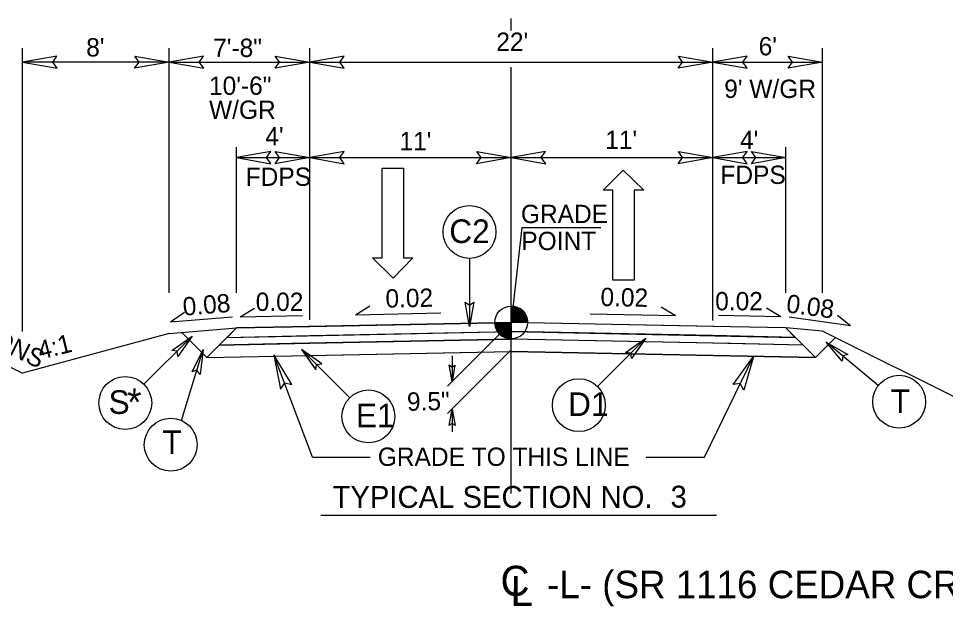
# Model space of a CAD drawing. Extents: x 573732 to 574187, y -53389 to -53257.
# Drawn here: x 573830.3 to 573880.9, y -53355.4 to -53323.3 of the extents above; entities that cross this region are included whole.
import ezdxf

# ---------------------------------------------------------------- set-up
doc = ezdxf.new("R2010")
doc.units = 0
for name, color, linetype in [('Old_Level_11', 7, 'Continuous'), ('Prop Dimension', 7, 'Continuous'), ('Prop Lane Arrow CELL', 7, 'Continuous'), ('Prop Shade Light', 7, 'Continuous'), ('Prop Shade Medium', 7, 'Continuous'), ('Typical Grade Point Symbol CELL', 7, 'Continuous'), ('Typical ID Circle CELL', 7, 'Continuous'), ('Typical Pavement Slope CELL', 7, 'Continuous'), ('Typical Pavement Slope Information CELL', 7, 'Continuous'), ('Typical Shoulder Slope CELL', 7, 'Continuous'), ('Typical Shoulder Slope Information CELL', 7, 'Continuous'), ('Typical Slope Point Local CELL', 7, 'Continuous'), ('Typical Terminator CELL', 7, 'Continuous'), ('Typical Text Centerline CELL', 7, 'Continuous'), ('Typical Text General CELL', 7, 'Continuous'), ('Typical Text Grade Point CELL', 7, 'Continuous'), ('Typical Text ID Circle CELL', 7, 'Continuous'), ('Typical Text Label CELL', 7, 'Continuous')]:
    doc.layers.add(name, color=color, linetype=linetype)

msp = doc.modelspace()

# ---------------------------------------------------------------- linework, layer by layer
at = {"layer": 'Old_Level_11'}
for points in [[(573854.103, -53342.22), (573853.948, -53343.12), (573853.788, -53342.215), (573853.948, -53342.33)], [(573853.793, -53345.52), (573853.948, -53344.62), (573854.108, -53345.525), (573853.948, -53345.41)]]:
    msp.add_lwpolyline(points, close=True, dxfattribs=at)
at = {"layer": 'Prop Dimension'}
for p, q in [((573830.501, -53340.385), (573830.501, -53324.924)), ((573838.501, -53338.27), (573838.501, -53324.924)), ((573846.171, -53339.759), (573846.171, -53324.924)), ((573868.171, -53339.784), (573868.171, -53324.924)), ((573874.171, -53338.27), (573874.171, -53324.924)), ((573838.501, -53325.68), (573830.501, -53325.68)), ((573838.501, -53325.68), (573846.171, -53325.68)), ((573846.171, -53325.68), (573868.171, -53325.68)), ((573868.171, -53325.68), (573874.171, -53325.68)), ((573842.171, -53338.27), (573842.171, -53330.32)), ((573872.171, -53338.27), (573872.171, -53330.32)), ((573842.171, -53330.896), (573846.171, -53330.896)), ((573846.171, -53330.896), (573857.171, -53330.896)), ((573857.171, -53330.896), (573868.171, -53330.896)), ((573868.171, -53330.896), (573872.171, -53330.896)), ((573857.747, -53334.719), (573857.171, -53339.896)), ((573857.747, -53334.719), (573862.067, -53334.719)), ((573857.172, -53339.897), (573853.701, -53343.367)), ((573857.172, -53341.397), (573853.701, -53344.868)), ((573846.331, -53347.251), (573844.209, -53341.657)), ((573853.948, -53341.723), (573853.948, -53343.12)), ((573867.717, -53347.251), (573870.391, -53341.745)), ((573853.948, -53344.62), (573853.948, -53345.874)), ((573846.331, -53347.251), (573849.471, -53347.251)), ((573864.533, -53347.251), (573867.717, -53347.251))]:
    msp.add_line(p, q, dxfattribs=at)
at = {"layer": 'Prop Lane Arrow CELL'}
for p, q in [((573850.13, -53336.375), (573850.13, -53331.475)), ((573850.13, -53331.475), (573851.285, -53331.475)), ((573851.285, -53331.475), (573851.285, -53336.375)), ((573862.201, -53332.683), (573863.286, -53331.581)), ((573863.286, -53331.581), (573864.406, -53332.683)), ((573862.726, -53332.683), (573862.201, -53332.683)), ((573862.726, -53337.583), (573862.726, -53332.683)), ((573864.406, -53332.683), (573863.881, -53332.683)), ((573863.881, -53332.683), (573863.881, -53337.583)), ((573850.725, -53337.477), (573849.605, -53336.375)), ((573849.605, -53336.375), (573850.13, -53336.375)), ((573851.81, -53336.375), (573850.725, -53337.477)), ((573851.285, -53336.375), (573851.81, -53336.375)), ((573863.881, -53337.583), (573862.726, -53337.583))]:
    msp.add_line(p, q, dxfattribs=at)
at = {"layer": 'Prop Shade Light'}
for p, q in [((573857.171, -53339.896), (573845.175, -53340.136)), ((573869.166, -53340.136), (573857.171, -53339.896)), ((573842.171, -53340.198), (573841.66, -53340.708)), ((573845.175, -53340.136), (573842.171, -53340.198)), ((573845.185, -53340.636), (573857.161, -53340.397)), ((573857.161, -53340.397), (573857.161, -53340.396)), ((573857.161, -53340.396), (573857.171, -53340.396)), ((573857.171, -53340.396), (573857.181, -53340.396)), ((573857.181, -53340.396), (573857.181, -53340.397)), ((573857.181, -53340.397), (573869.156, -53340.636)), ((573872.171, -53340.198), (573869.166, -53340.136)), ((573872.681, -53340.708), (573872.171, -53340.198)), ((573841.66, -53340.708), (573845.185, -53340.636)), ((573869.156, -53340.636), (573872.681, -53340.708))]:
    msp.add_line(p, q, dxfattribs=at)
at = {"layer": 'Prop Shade Medium'}
for p, q in [((573841.234, -53341.134), (573840.554, -53341.815)), ((573845.194, -53341.053), (573841.234, -53341.134)), ((573873.107, -53341.134), (573869.148, -53341.053)), ((573873.787, -53341.815), (573873.107, -53341.134)), ((573840.554, -53341.815), (573845.207, -53341.719)), ((573845.207, -53341.719), (573857.139, -53341.481)), ((573857.139, -53341.481), (573857.139, -53341.479)), ((573857.139, -53341.479), (573857.171, -53341.48)), ((573857.171, -53341.48), (573857.202, -53341.479)), ((573857.202, -53341.479), (573857.202, -53341.481)), ((573857.202, -53341.481), (573869.135, -53341.719)), ((573869.135, -53341.719), (573873.787, -53341.815))]:
    msp.add_line(p, q, dxfattribs=at)
for points in [[(573857.171, -53340.813), (573857.152, -53340.814), (573845.194, -53341.053)], [(573869.148, -53341.053), (573857.189, -53340.814), (573857.171, -53340.813)]]:
    msp.add_lwpolyline(points, dxfattribs=at)
at = {"layer": 'Typical Grade Point Symbol CELL'}
for p, q in [((573857.172, -53339.897), (573857.172, -53339.001)), ((573856.276, -53339.897), (573857.172, -53339.897)), ((573857.17, -53340.792), (573857.172, -53339.897)), ((573857.172, -53339.897), (573857.17, -53340.792)), ((573858.067, -53339.897), (573857.172, -53339.897))]:
    msp.add_line(p, q, dxfattribs=at)
for points in [[(573857.18, -53339.001), (573857.18, -53339.001), (573857.18, -53339.897)], [(573857.197, -53339.001), (573857.197, -53339.897)], [(573857.215, -53339.003), (573857.215, -53339.897)], [(573857.233, -53339.003), (573857.233, -53339.897)], [(573857.251, -53339.005), (573857.251, -53339.897)], [(573857.269, -53339.007), (573857.269, -53339.897)], [(573857.287, -53339.009), (573857.287, -53339.897)], [(573857.305, -53339.011), (573857.305, -53339.897)], [(573857.323, -53339.013), (573857.323, -53339.897)], [(573857.341, -53339.017), (573857.341, -53339.897)], [(573857.359, -53339.021), (573857.359, -53339.897)], [(573857.377, -53339.025), (573857.377, -53339.897)], [(573857.394, -53339.029), (573857.394, -53339.897)], [(573857.412, -53339.035), (573857.412, -53339.897)], [(573857.43, -53339.039), (573857.43, -53339.897)], [(573857.448, -53339.045), (573857.448, -53339.897)], [(573857.466, -53339.051), (573857.466, -53339.897)], [(573857.484, -53339.057), (573857.484, -53339.897)], [(573857.502, -53339.065), (573857.502, -53339.897)], [(573857.52, -53339.073), (573857.52, -53339.897)], [(573857.538, -53339.081), (573857.538, -53339.897)], [(573857.556, -53339.089), (573857.556, -53339.897)], [(573857.573, -53339.097), (573857.573, -53339.897)], [(573857.591, -53339.107), (573857.591, -53339.897)], [(573857.609, -53339.117), (573857.609, -53339.897)], [(573857.627, -53339.127), (573857.627, -53339.897)], [(573857.645, -53339.137), (573857.645, -53339.897)], [(573857.663, -53339.149), (573857.663, -53339.897)], [(573857.681, -53339.16), (573857.681, -53339.897)], [(573857.699, -53339.174), (573857.699, -53339.897)], [(573857.717, -53339.186), (573857.717, -53339.897)], [(573857.735, -53339.2), (573857.735, -53339.897)], [(573857.752, -53339.216), (573857.752, -53339.897)], [(573857.77, -53339.232), (573857.77, -53339.897)], [(573857.788, -53339.248), (573857.788, -53339.897)], [(573857.806, -53339.266), (573857.806, -53339.897)], [(573857.824, -53339.284), (573857.824, -53339.897)], [(573857.842, -53339.304), (573857.842, -53339.897)], [(573857.86, -53339.326), (573857.86, -53339.897)], [(573857.878, -53339.347), (573857.878, -53339.897)], [(573857.896, -53339.371), (573857.896, -53339.897)], [(573857.914, -53339.397), (573857.914, -53339.897)], [(573856.28, -53339.897), (573856.28, -53339.994)], [(573856.298, -53339.897), (573856.298, -53340.099)], [(573856.316, -53339.897), (573856.316, -53340.163)], [(573856.334, -53339.897), (573856.334, -53340.217)], [(573856.352, -53339.897), (573856.352, -53340.259)], [(573856.37, -53339.897), (573856.37, -53340.296)], [(573856.388, -53339.897), (573856.388, -53340.33)], [(573856.406, -53339.897), (573856.406, -53340.362)], [(573856.424, -53339.897), (573856.424, -53340.39)], [(573856.442, -53339.897), (573856.442, -53340.416)], [(573856.459, -53339.897), (573856.459, -53340.44)], [(573856.477, -53339.897), (573856.477, -53340.461)], [(573856.495, -53339.897), (573856.495, -53340.483)], [(573856.513, -53339.897), (573856.513, -53340.503)], [(573856.531, -53339.897), (573856.531, -53340.523)], [(573856.549, -53339.897), (573856.549, -53340.541)], [(573856.567, -53339.897), (573856.567, -53340.557)], [(573856.585, -53339.897), (573856.585, -53340.573)], [(573856.603, -53339.897), (573856.603, -53340.589)], [(573856.621, -53339.897), (573856.621, -53340.603)], [(573856.639, -53339.897), (573856.639, -53340.617)], [(573856.656, -53339.897), (573856.656, -53340.628)], [(573856.674, -53339.897), (573856.674, -53340.64)], [(573856.692, -53339.897), (573856.692, -53340.652)], [(573856.71, -53339.897), (573856.71, -53340.664)], [(573856.728, -53339.897), (573856.728, -53340.674)], [(573856.746, -53339.897), (573856.746, -53340.684)], [(573856.764, -53339.897), (573856.764, -53340.694)], [(573856.782, -53339.897), (573856.782, -53340.702)], [(573856.8, -53339.897), (573856.8, -53340.71)], [(573856.818, -53339.897), (573856.818, -53340.718)], [(573856.835, -53339.897), (573856.835, -53340.726)], [(573856.853, -53339.897), (573856.853, -53340.734)], [(573856.871, -53339.897), (573856.871, -53340.74)], [(573856.889, -53339.897), (573856.889, -53340.746)], [(573856.907, -53339.897), (573856.907, -53340.752)], [(573856.925, -53339.897), (573856.925, -53340.756)], [(573856.943, -53339.897), (573856.943, -53340.762)], [(573856.961, -53339.897), (573856.961, -53340.766)], [(573856.979, -53339.897), (573856.979, -53340.77)], [(573856.997, -53339.897), (573856.997, -53340.774)], [(573857.014, -53339.897), (573857.014, -53340.778)], [(573857.032, -53339.897), (573857.032, -53340.78)], [(573857.05, -53339.897), (573857.05, -53340.784)], [(573857.068, -53339.897), (573857.068, -53340.786)], [(573857.086, -53339.897), (573857.086, -53340.788)], [(573857.104, -53339.897), (573857.104, -53340.79)], [(573857.122, -53339.897), (573857.122, -53340.79)], [(573857.14, -53339.897), (573857.14, -53340.792)], [(573857.158, -53339.897), (573857.158, -53340.792), (573857.158, -53340.792)], [(573857.932, -53339.425), (573857.932, -53339.897)], [(573857.949, -53339.455), (573857.949, -53339.897)], [(573857.967, -53339.487), (573857.967, -53339.897)], [(573857.985, -53339.524), (573857.985, -53339.897)], [(573858.003, -53339.566), (573858.003, -53339.897)], [(573858.021, -53339.616), (573858.021, -53339.897)], [(573858.039, -53339.678), (573858.039, -53339.897)], [(573858.057, -53339.769), (573858.057, -53339.897)]]:
    msp.add_lwpolyline(points, dxfattribs=at)
msp.add_circle((573857.171, -53339.896), 0.895, dxfattribs=at)
for start, end in [(359.9905, 89.9905), (179.9905, 269.9905)]:
    msp.add_arc((573857.171, -53339.896), 0.895, start, end, dxfattribs=at)
at = {"layer": 'Typical ID Circle CELL'}
for p, q in [((573854.895, -53336.395), (573854.895, -53340.123)), ((573837.122, -53343.272), (573839.759, -53340.636)), ((573861.885, -53343.387), (573864.523, -53340.752)), ((573839.178, -53345.252), (573840.357, -53341.379)), ((573848.357, -53344.005), (573845.72, -53341.369)), ((573877.21, -53343.336), (573874.369, -53340.97))]:
    msp.add_line(p, q, dxfattribs=at)
for centre in [(573854.895, -53334.953), (573836.103, -53344.292), (573878.349, -53344.223), (573860.866, -53344.408), (573849.376, -53345.025), (573838.585, -53346.567)]:
    msp.add_circle(centre, 1.443, dxfattribs=at)
at = {"layer": 'Typical Pavement Slope CELL'}
for p, q in [((573846.171, -53340.116), (573857.171, -53339.896)), ((573868.171, -53340.116), (573857.171, -53339.896)), ((573846.171, -53340.616), (573857.181, -53340.396)), ((573868.171, -53340.616), (573857.161, -53340.396)), ((573846.171, -53341.033), (573857.171, -53340.813)), ((573868.171, -53341.033), (573857.171, -53340.813)), ((573846.171, -53341.7), (573857.171, -53341.48)), ((573868.171, -53341.7), (573857.171, -53341.48))]:
    msp.add_line(p, q, dxfattribs=at)
at = {"layer": 'Typical Pavement Slope Information CELL'}
for p, q in [((573838.579, -53339.86), (573839.332, -53339.34)), ((573842.377, -53339.581), (573843.16, -53339.108)), ((573848.676, -53339.471), (573849.459, -53338.997)), ((573848.676, -53339.471), (573853.336, -53339.377)), ((573866.15, -53339.531), (573865.367, -53339.058)), ((573871.889, -53339.581), (573871.106, -53339.108)), ((573838.579, -53339.86), (573841.964, -53339.585)), ((573842.377, -53339.581), (573845.772, -53339.513)), ((573866.15, -53339.531), (573861.49, -53339.438)), ((573871.889, -53339.581), (573868.494, -53339.513)), ((573875.701, -53340.075), (573872.339, -53339.599)), ((573875.701, -53340.075), (573874.981, -53339.511))]:
    msp.add_line(p, q, dxfattribs=at)
at = {"layer": 'Typical Shoulder Slope CELL'}
for p, q in [((573838.501, -53340.503), (573842.171, -53340.198)), ((573840.554, -53341.815), (573842.171, -53340.198)), ((573842.171, -53340.198), (573846.171, -53340.116)), ((573872.171, -53340.198), (573868.171, -53340.116)), ((573874.171, -53340.364), (573872.171, -53340.198)), ((573873.787, -53341.815), (573872.171, -53340.198)), ((573840.554, -53341.815), (573839.185, -53340.446)), ((573841.66, -53340.708), (573846.171, -53340.616)), ((573872.681, -53340.708), (573868.171, -53340.616)), ((573873.787, -53341.815), (573874.882, -53340.72)), ((573841.234, -53341.134), (573846.171, -53341.033)), ((573873.107, -53341.134), (573868.171, -53341.033)), ((573840.554, -53341.815), (573846.171, -53341.7)), ((573873.787, -53341.815), (573868.171, -53341.7))]:
    msp.add_line(p, q, dxfattribs=at)
at = {"layer": 'Typical Slope Point Local CELL'}
for p, q in [((573816.884, -53335.847), (573830.501, -53342.655)), ((573896.67, -53351.615), (573874.171, -53340.364)), ((573838.501, -53340.503), (573830.501, -53342.655))]:
    msp.add_line(p, q, dxfattribs=at)
at = {"layer": 'Typical Terminator CELL'}
for points in [[(573832.375, -53325.357), (573830.501, -53325.68), (573832.386, -53326.013), (573832.146, -53325.68)], [(573836.626, -53325.357), (573838.501, -53325.68), (573836.615, -53326.013), (573836.855, -53325.68)], [(573840.375, -53325.357), (573838.501, -53325.68), (573840.386, -53326.013), (573840.146, -53325.68)], [(573844.296, -53325.357), (573846.171, -53325.68), (573844.285, -53326.013), (573844.525, -53325.68)], [(573848.045, -53325.357), (573846.171, -53325.68), (573848.056, -53326.013), (573847.816, -53325.68)], [(573866.296, -53325.357), (573868.171, -53325.68), (573866.285, -53326.013), (573866.525, -53325.68)], [(573870.045, -53325.357), (573868.171, -53325.68), (573870.056, -53326.013), (573869.816, -53325.68)], [(573872.296, -53325.357), (573874.171, -53325.68), (573872.285, -53326.013), (573872.525, -53325.68)], [(573844.045, -53330.573), (573842.171, -53330.896), (573844.056, -53331.229), (573843.816, -53330.896)], [(573844.296, -53330.573), (573846.171, -53330.896), (573844.285, -53331.229), (573844.525, -53330.896)], [(573848.045, -53330.573), (573846.171, -53330.896), (573848.056, -53331.229), (573847.816, -53330.896)], [(573855.296, -53330.573), (573857.171, -53330.896), (573855.285, -53331.229), (573855.525, -53330.896)], [(573859.045, -53330.573), (573857.171, -53330.896), (573859.056, -53331.229), (573858.816, -53330.896)], [(573866.296, -53330.573), (573868.171, -53330.896), (573866.285, -53331.229), (573866.525, -53330.896)], [(573870.045, -53330.573), (573868.171, -53330.896), (573870.056, -53331.229), (573869.816, -53330.896)], [(573870.296, -53330.573), (573872.171, -53330.896), (573870.285, -53331.229), (573870.525, -53330.896)], [(573855.125, -53338.788), (573854.895, -53340.123), (573854.658, -53338.78), (573854.895, -53338.951)], [(573838.652, -53341.418), (573839.759, -53340.636), (573838.977, -53341.754), (573838.93, -53341.465)], [(573863.415, -53341.533), (573864.523, -53340.752), (573863.741, -53341.869), (573863.694, -53341.58)], [(573839.748, -53342.589), (573840.357, -53341.379), (573840.193, -53342.733), (573840.016, -53342.5)], [(573846.827, -53342.151), (573845.72, -53341.369), (573846.502, -53342.487), (573846.549, -53342.198)], [(573875.248, -53342.002), (573874.369, -53340.97), (573875.553, -53341.647), (573875.27, -53341.721)], [(573845.192, -53343.285), (573844.209, -53341.657), (573844.585, -53343.534), (573844.808, -53343.189)], [(573869.281, -53343.291), (573870.391, -53341.745), (573869.867, -53343.587), (573869.672, -53343.226)]]:
    msp.add_lwpolyline(points, close=True, dxfattribs=at)
at = {"layer": 'Typical Text Centerline CELL'}
for p, q in [((573857.171, -53323.963), (573857.171, -53323.307)), ((573857.171, -53349.241), (573857.171, -53325.961))]:
    msp.add_line(p, q, dxfattribs=at)
at = {"layer": 'Typical Text Label CELL'}
msp.add_line((573846.778, -53350.417), (573868.383, -53350.417), dxfattribs=at)

# ---------------------------------------------------------------- texts
at = {"layer": 'Typical Pavement Slope Information CELL'}
for s, rotation, p in [("22'", 360, (573856.359, -53325.072)), ("8'", 360, (573833.971, -53325.377)), ('7\'-8"', 360, (573840.903, -53325.405)), ("6'", 360, (573870.68, -53325.316)), ("9' W/GR", 360, (573868.802, -53327.642)), ("4'", 360, (573843.747, -53330.23)), ("11'", 360, (573851.074, -53330.496)), ("11'", 360, (573862.304, -53330.428)), ("4'", 360, (573869.661, -53330.436)), ('FDPS', 360, (573868.596, -53332.335)), ('FDPS', 360, (573842.677, -53332.439)), ('0.02', 1.1457, (573850.317, -53339.088)), ('0.02', 358.8543, (573862.036, -53338.996))]:
    msp.add_text(s, height=1, rotation=rotation, dxfattribs=at).set_placement(p)
for s, p in [('10\'-6"', (573840.676, -53327.472)), ('W/GR', (573840.676, -53328.783))]:
    msp.add_text(s, height=1, dxfattribs=at).set_placement(p)
at = {"layer": 'Typical Shoulder Slope Information CELL'}
for s, rotation, p in [('0.08', 4.7615, (573839.283, -53339.532)), ('0.02', 360, (573843.225, -53339.267)), ('0.02', 360, (573868.308, -53339.234)), ('0.08', 352.4054, (573872.148, -53339.341)), ('9.5"', 1.1457, (573851.492, -53344.719))]:
    msp.add_text(s, height=1, rotation=rotation, dxfattribs=at).set_placement(p)
at = {"layer": 'Typical Slope Point Local CELL'}
for s, rotation, p in [('VAR SEE X-SECTIONS', 333.435, (573818.555, -53336.022)), ('4:1', 14.0362, (573831.466, -53341.931))]:
    msp.add_text(s, height=1, rotation=rotation, dxfattribs=at).set_placement(p)
at = {"layer": 'Typical Text Centerline CELL'}
msp.add_text('C', height=1.64, dxfattribs=at).set_placement((573856.59, -53354.817))
for s, height, rotation, p in [('-L- (SR 1116 CEDAR CREEK RD)', 1.5, 360, (573859.133, -53354.947)), ('L', 1.641, 359.9469, (573857.135, -53355.377))]:
    msp.add_text(s, height=height, rotation=rotation, dxfattribs=at).set_placement(p)
at = {"layer": 'Typical Text General CELL'}
msp.add_text('GRADE TO THIS LINE', height=1, dxfattribs=at).set_placement((573849.889, -53347.725))
at = {"layer": 'Typical Text Grade Point CELL'}
for s, p in [('GRADE', (573857.703, -53334.473)), ('POINT', (573857.724, -53335.945))]:
    msp.add_text(s, height=1, dxfattribs=at).set_placement(p)
at = {"layer": 'Typical Text ID Circle CELL'}
for s, height, p in [('C2', 1.2912, (573853.792, -53335.563)), ('S', 1.291, (573835.193, -53344.887)), ('*', 1.5, (573836.21, -53344.995)), ('D1', 1.2912, (573860.275, -53345.002)), ('T ', 1.2912, (573877.888, -53344.843)), ('T', 1.291, (573838.128, -53347.073))]:
    msp.add_text(s, height=height, dxfattribs=at).set_placement(p)
msp.add_text('E1', height=1.2912, rotation=360, dxfattribs=at).set_placement((573848.695, -53345.62))
at = {"layer": 'Typical Text Label CELL'}
for s, height, p in [('TYPICAL SECTION NO.  ', 1.19356, (573847.419, -53350.017)), ('3 ', 1.1936, (573865.871, -53350.001))]:
    msp.add_text(s, height=height, rotation=360, dxfattribs=at).set_placement(p)

doc.saveas('drawing.dxf')
